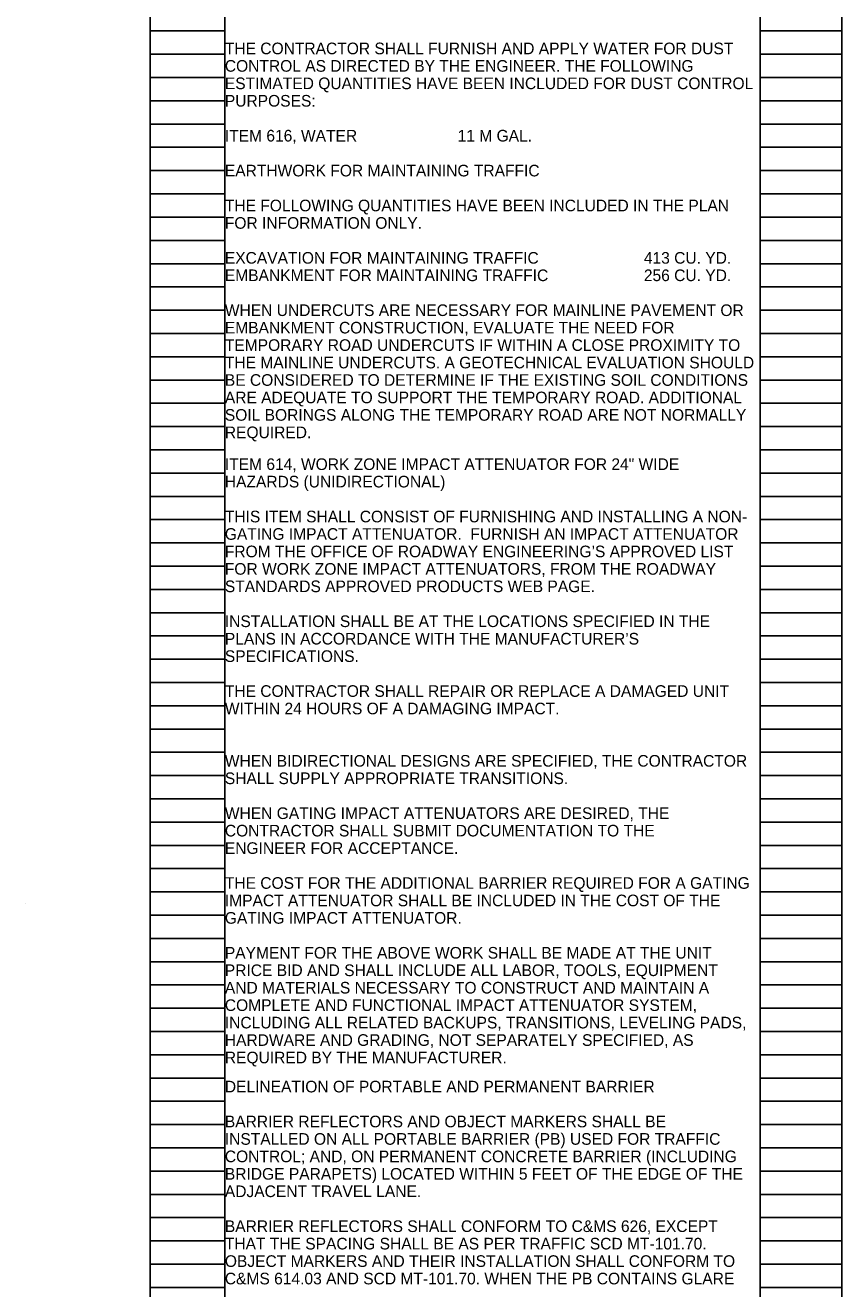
# Model space of a CAD drawing. Extents: x 11124 to 11156, y 1608 to 1730.
# Drawn here: x 11124.4 to 11134.22, y 1684.27 to 1699.48 of the extents above; entities that cross this region are included whole.
import ezdxf

# ---------------------------------------------------------------- set-up
doc = ezdxf.new("R2010")
doc.units = 0
doc.layers.add('SC_Scratch1', color=7, linetype='Continuous')
doc.layers.add('SH_Text', color=7, linetype='Continuous')

msp = doc.modelspace()

# ---------------------------------------------------------------- linework, layer by layer
at = {"layer": 'SC_Scratch1'}
for p, q in [((11125.896, 1689.889), (11125.896, 1710.049)), ((11126.796, 1689.889), (11126.796, 1710.049)), ((11133.236, 1689.889), (11133.236, 1710.049)), ((11134.216, 1689.889), (11134.216, 1710.049)), ((11125.896, 1699.409), (11126.796, 1699.409)), ((11133.236, 1699.409), (11134.216, 1699.409)), ((11125.896, 1699.129), (11126.796, 1699.129)), ((11133.236, 1699.129), (11134.216, 1699.129)), ((11125.896, 1698.849), (11126.796, 1698.849)), ((11133.236, 1698.849), (11134.216, 1698.849)), ((11125.896, 1698.569), (11126.796, 1698.569)), ((11133.236, 1698.569), (11134.216, 1698.569)), ((11125.896, 1698.289), (11126.796, 1698.289)), ((11133.236, 1698.289), (11134.216, 1698.289)), ((11125.896, 1698.009), (11126.796, 1698.009)), ((11133.236, 1698.009), (11134.216, 1698.009)), ((11125.896, 1697.729), (11126.796, 1697.729)), ((11133.236, 1697.729), (11134.216, 1697.729)), ((11125.896, 1697.449), (11126.796, 1697.449)), ((11133.236, 1697.449), (11134.216, 1697.449)), ((11125.896, 1697.169), (11126.796, 1697.169)), ((11133.236, 1697.169), (11134.216, 1697.169)), ((11125.896, 1696.889), (11126.796, 1696.889)), ((11133.236, 1696.889), (11134.216, 1696.889)), ((11125.896, 1696.609), (11126.796, 1696.609)), ((11133.236, 1696.609), (11134.216, 1696.609)), ((11125.896, 1696.329), (11126.796, 1696.329)), ((11133.236, 1696.329), (11134.216, 1696.329)), ((11125.896, 1696.049), (11126.796, 1696.049)), ((11133.236, 1696.049), (11134.216, 1696.049)), ((11125.896, 1695.769), (11126.796, 1695.769)), ((11133.236, 1695.769), (11134.216, 1695.769)), ((11125.896, 1695.489), (11126.796, 1695.489)), ((11133.236, 1695.489), (11134.216, 1695.489)), ((11125.896, 1695.209), (11126.796, 1695.209)), ((11133.236, 1695.209), (11134.216, 1695.209)), ((11125.896, 1694.929), (11126.796, 1694.929)), ((11133.236, 1694.929), (11134.216, 1694.929)), ((11125.896, 1694.649), (11126.796, 1694.649)), ((11133.236, 1694.649), (11134.216, 1694.649)), ((11125.896, 1694.369), (11126.796, 1694.369)), ((11133.236, 1694.369), (11134.216, 1694.369)), ((11125.896, 1694.089), (11126.796, 1694.089)), ((11133.236, 1694.089), (11134.216, 1694.089)), ((11125.896, 1693.809), (11126.796, 1693.809)), ((11133.236, 1693.809), (11134.216, 1693.809)), ((11125.896, 1693.529), (11126.796, 1693.529)), ((11133.236, 1693.529), (11134.216, 1693.529)), ((11125.896, 1693.249), (11126.796, 1693.249)), ((11133.236, 1693.249), (11134.216, 1693.249)), ((11125.896, 1692.969), (11126.796, 1692.969)), ((11133.236, 1692.969), (11134.216, 1692.969)), ((11125.896, 1692.689), (11126.796, 1692.689)), ((11133.236, 1692.689), (11134.216, 1692.689)), ((11125.896, 1692.409), (11126.796, 1692.409)), ((11133.236, 1692.409), (11134.216, 1692.409)), ((11125.896, 1692.129), (11126.796, 1692.129)), ((11133.236, 1692.129), (11134.216, 1692.129)), ((11125.896, 1691.849), (11126.796, 1691.849)), ((11133.236, 1691.849), (11134.216, 1691.849)), ((11125.896, 1691.569), (11126.796, 1691.569)), ((11133.236, 1691.569), (11134.216, 1691.569)), ((11125.896, 1691.289), (11126.796, 1691.289)), ((11133.236, 1691.289), (11134.216, 1691.289)), ((11125.896, 1691.009), (11126.796, 1691.009)), ((11133.236, 1691.009), (11134.216, 1691.009)), ((11125.896, 1690.729), (11126.796, 1690.729)), ((11133.236, 1690.729), (11134.216, 1690.729)), ((11125.896, 1690.449), (11126.796, 1690.449)), ((11133.236, 1690.449), (11134.216, 1690.449)), ((11125.896, 1690.169), (11126.796, 1690.169)), ((11133.236, 1690.169), (11134.216, 1690.169)), ((11125.896, 1689.889), (11126.796, 1689.889)), ((11125.896, 1669.729), (11125.896, 1689.889)), ((11125.896, 1689.889), (11126.796, 1689.889)), ((11126.796, 1669.729), (11126.796, 1689.889)), ((11133.236, 1689.889), (11134.216, 1689.889)), ((11133.236, 1669.729), (11133.236, 1689.889)), ((11133.236, 1689.889), (11134.216, 1689.889)), ((11134.216, 1669.729), (11134.216, 1689.889)), ((11125.896, 1689.609), (11126.796, 1689.609)), ((11133.236, 1689.609), (11134.216, 1689.609)), ((11125.896, 1689.329), (11126.796, 1689.329)), ((11133.236, 1689.329), (11134.216, 1689.329)), ((11124.396, 1688.909), (11124.396, 1688.909)), ((11125.896, 1689.049), (11126.796, 1689.049)), ((11133.236, 1689.049), (11134.216, 1689.049)), ((11125.896, 1688.769), (11126.796, 1688.769)), ((11133.236, 1688.769), (11134.216, 1688.769)), ((11125.896, 1688.489), (11126.796, 1688.489)), ((11133.236, 1688.489), (11134.216, 1688.489)), ((11125.896, 1688.209), (11126.796, 1688.209)), ((11133.236, 1688.209), (11134.216, 1688.209)), ((11125.896, 1687.929), (11126.796, 1687.929)), ((11133.236, 1687.929), (11134.216, 1687.929)), ((11125.896, 1687.649), (11126.796, 1687.649)), ((11133.236, 1687.649), (11134.216, 1687.649)), ((11125.896, 1687.369), (11126.796, 1687.369)), ((11133.236, 1687.369), (11134.216, 1687.369)), ((11125.896, 1687.089), (11126.796, 1687.089)), ((11133.236, 1687.089), (11134.216, 1687.089)), ((11125.896, 1686.809), (11126.796, 1686.809)), ((11133.236, 1686.809), (11134.216, 1686.809)), ((11125.896, 1686.529), (11126.796, 1686.529)), ((11133.236, 1686.529), (11134.216, 1686.529)), ((11125.896, 1686.249), (11126.796, 1686.249)), ((11133.236, 1686.249), (11134.216, 1686.249)), ((11125.896, 1685.969), (11126.796, 1685.969)), ((11133.236, 1685.969), (11134.216, 1685.969)), ((11125.896, 1685.689), (11126.796, 1685.689)), ((11133.236, 1685.689), (11134.216, 1685.689)), ((11125.896, 1685.409), (11126.796, 1685.409)), ((11133.236, 1685.409), (11134.216, 1685.409)), ((11125.896, 1685.129), (11126.796, 1685.129)), ((11133.236, 1685.129), (11134.216, 1685.129)), ((11125.896, 1684.849), (11126.796, 1684.849)), ((11133.236, 1684.849), (11134.216, 1684.849)), ((11125.896, 1684.569), (11126.796, 1684.569)), ((11133.236, 1684.569), (11134.216, 1684.569)), ((11125.896, 1684.289), (11126.796, 1684.289)), ((11133.236, 1684.289), (11134.216, 1684.289))]:
    msp.add_line(p, q, dxfattribs=at)

# ---------------------------------------------------------------- texts
at = {"layer": 'SH_Text'}
for s, p in [('THE CONTRACTOR SHALL FURNISH AND APPLY WATER FOR DUST ', (11126.796, 1699.129)), ('CONTROL AS DIRECTED BY THE ENGINEER. THE FOLLOWING ', (11126.796, 1698.919)), ('ESTIMATED QUANTITIES HAVE BEEN INCLUDED FOR DUST CONTROL ', (11126.796, 1698.709)), ('PURPOSES:', (11126.796, 1698.499)), ('ITEM 616, WATER', (11126.796, 1698.079)), ('11 M GAL.', (11129.596, 1698.079)), ('EARTHWORK FOR MAINTAINING TRAFFIC', (11126.796, 1697.659)), ('THE FOLLOWING QUANTITIES HAVE BEEN INCLUDED IN THE PLAN ', (11126.796, 1697.239)), ('FOR INFORMATION ONLY.', (11126.796, 1697.029)), ('EXCAVATION FOR MAINTAINING TRAFFIC', (11126.796, 1696.609)), ('413 CU. YD.', (11131.836, 1696.609)), ('EMBANKMENT FOR MAINTAINING TRAFFIC', (11126.796, 1696.399)), ('256 CU. YD.', (11131.836, 1696.399)), ('WHEN UNDERCUTS ARE NECESSARY FOR MAINLINE PAVEMENT OR ', (11126.796, 1695.979)), ('EMBANKMENT CONSTRUCTION, EVALUATE THE NEED FOR ', (11126.796, 1695.769)), ('TEMPORARY ROAD UNDERCUTS IF WITHIN A CLOSE PROXIMITY TO ', (11126.796, 1695.559)), ('THE MAINLINE UNDERCUTS. A GEOTECHNICAL EVALUATION SHOULD ', (11126.796, 1695.349)), ('BE CONSIDERED TO DETERMINE IF THE EXISTING SOIL CONDITIONS ', (11126.796, 1695.139)), ('ARE ADEQUATE TO SUPPORT THE TEMPORARY ROAD. ADDITIONAL ', (11126.796, 1694.929)), ('SOIL BORINGS ALONG THE TEMPORARY ROAD ARE NOT NORMALLY ', (11126.796, 1694.719)), ('REQUIRED.', (11126.796, 1694.509)), ('ITEM 614, WORK ZONE IMPACT ATTENUATOR FOR 24" WIDE ', (11126.796, 1694.126)), ('HAZARDS (UNIDIRECTIONAL)', (11126.796, 1693.916)), ('THIS ITEM SHALL CONSIST OF FURNISHING AND INSTALLING A NON-', (11126.796, 1693.496)), ('GATING IMPACT ATTENUATOR.  FURNISH AN IMPACT ATTENUATOR ', (11126.796, 1693.286)), ('FROM THE OFFICE OF ROADWAY ENGINEERING’S APPROVED LIST ', (11126.796, 1693.076)), ('FOR WORK ZONE IMPACT ATTENUATORS, FROM THE ROADWAY ', (11126.796, 1692.866)), ('STANDARDS APPROVED PRODUCTS WEB PAGE.', (11126.796, 1692.656)), ('INSTALLATION SHALL BE AT THE LOCATIONS SPECIFIED IN THE ', (11126.796, 1692.236)), ('PLANS IN ACCORDANCE WITH THE MANUFACTURER’S ', (11126.796, 1692.026)), ('SPECIFICATIONS.', (11126.796, 1691.816)), ('THE CONTRACTOR SHALL REPAIR OR REPLACE A DAMAGED UNIT ', (11126.796, 1691.396)), ('WITHIN 24 HOURS OF A DAMAGING IMPACT. ', (11126.796, 1691.186)), ('WHEN BIDIRECTIONAL DESIGNS ARE SPECIFIED, THE CONTRACTOR ', (11126.796, 1690.556)), ('SHALL SUPPLY APPROPRIATE TRANSITIONS.', (11126.796, 1690.346)), ('WHEN GATING IMPACT ATTENUATORS ARE DESIRED, THE ', (11126.796, 1689.926)), ('CONTRACTOR SHALL SUBMIT DOCUMENTATION TO THE', (11126.796, 1689.716)), ('ENGINEER FOR ACCEPTANCE.', (11126.796, 1689.506)), ('THE COST FOR THE ADDITIONAL BARRIER REQUIRED FOR A GATING ', (11126.796, 1689.086)), ('IMPACT ATTENUATOR SHALL BE INCLUDED IN THE COST OF THE ', (11126.796, 1688.876)), ('GATING IMPACT ATTENUATOR.', (11126.796, 1688.666)), ('PAYMENT FOR THE ABOVE WORK SHALL BE MADE AT THE UNIT ', (11126.796, 1688.246)), ('PRICE BID AND SHALL INCLUDE ALL LABOR, TOOLS, EQUIPMENT ', (11126.796, 1688.036)), ('AND MATERIALS NECESSARY TO CONSTRUCT AND MAINTAIN A ', (11126.796, 1687.826)), ('COMPLETE AND FUNCTIONAL IMPACT ATTENUATOR SYSTEM, ', (11126.796, 1687.616)), ('INCLUDING ALL RELATED BACKUPS, TRANSITIONS, LEVELING PADS, ', (11126.796, 1687.406)), ('HARDWARE AND GRADING, NOT SEPARATELY SPECIFIED, AS ', (11126.796, 1687.196)), ('REQUIRED BY THE MANUFACTURER.', (11126.796, 1686.986)), ('DELINEATION OF PORTABLE AND PERMANENT BARRIER', (11126.796, 1686.636)), ('BARRIER REFLECTORS AND OBJECT MARKERS SHALL BE ', (11126.796, 1686.216)), ('INSTALLED ON ALL PORTABLE BARRIER (PB) USED FOR TRAFFIC ', (11126.796, 1686.006)), ('CONTROL; AND, ON PERMANENT CONCRETE BARRIER (INCLUDING ', (11126.796, 1685.796)), ('BRIDGE PARAPETS) LOCATED WITHIN 5 FEET OF THE EDGE OF THE ', (11126.796, 1685.586)), ('ADJACENT TRAVEL LANE.', (11126.796, 1685.376)), ('BARRIER REFLECTORS SHALL CONFORM TO C&MS 626, EXCEPT ', (11126.796, 1684.956)), ('THAT THE SPACING SHALL BE AS PER TRAFFIC SCD MT-101.70. ', (11126.796, 1684.746)), ('OBJECT MARKERS AND THEIR INSTALLATION SHALL CONFORM TO ', (11126.796, 1684.536)), ('C&MS 614.03 AND SCD MT-101.70. WHEN THE PB CONTAINS GLARE ', (11126.796, 1684.326))]:
    msp.add_text(s, height=0.14, dxfattribs=at).set_placement(p)

doc.saveas('drawing.dxf')
